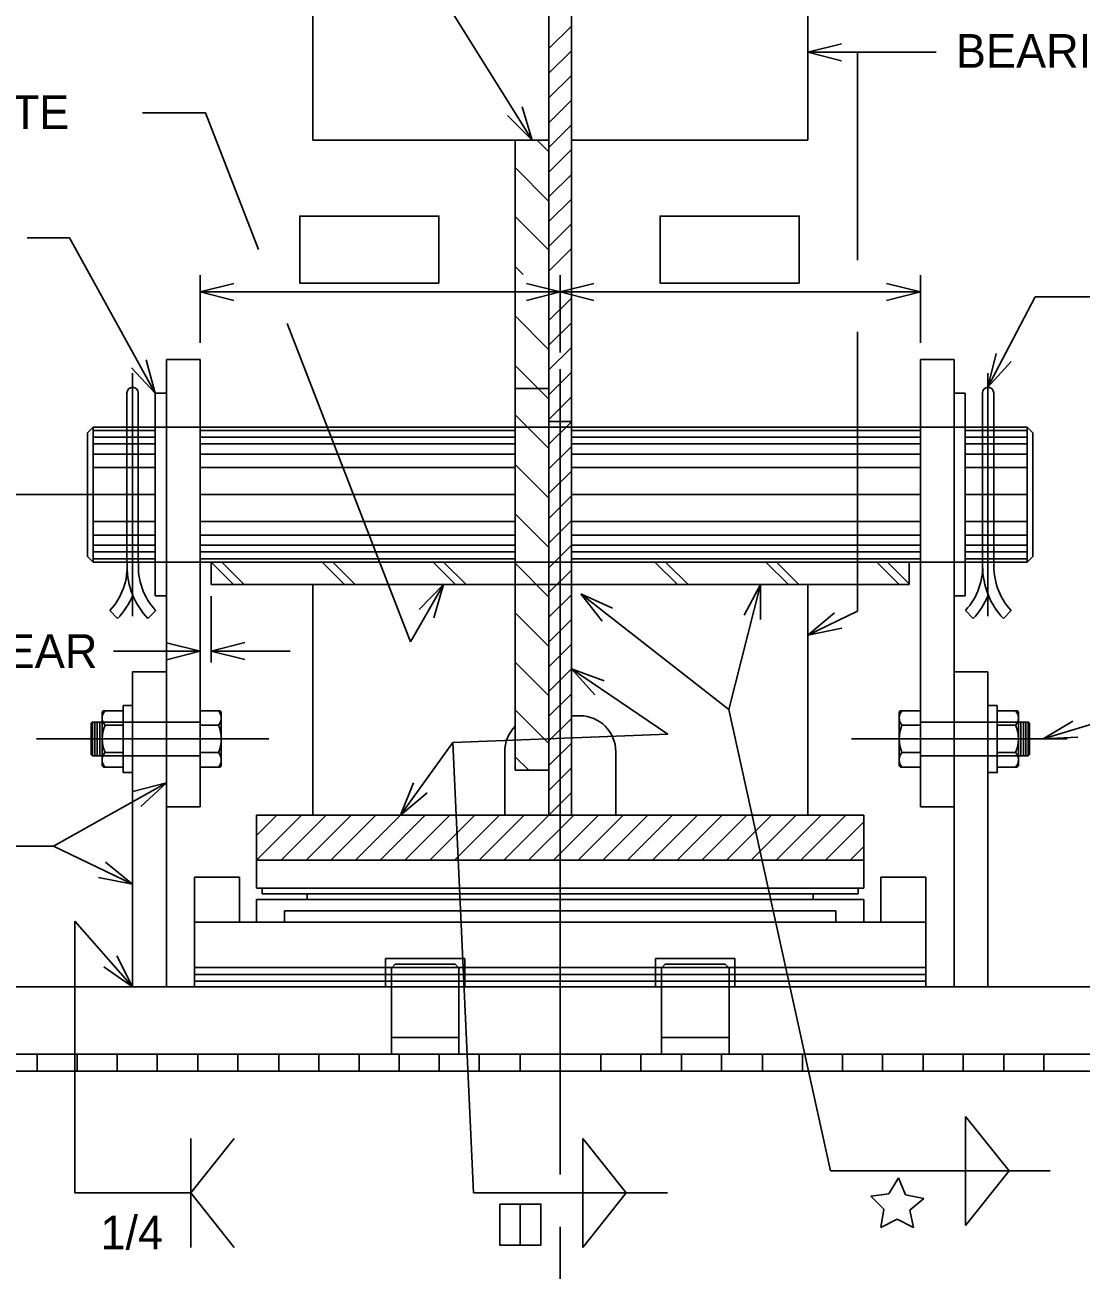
# Model space of a CAD drawing. Extents: x -1.5 to 34.7, y 2.5 to 26.9.
# Drawn here: x 12.425 to 16.336, y 17.426 to 22.038 of the extents above; entities that cross this region are included whole.
import ezdxf

# ---------------------------------------------------------------- set-up
doc = ezdxf.new("R2010")
doc.units = 0
doc.layers.add('Level 2', color=7, linetype='Continuous')

msp = doc.modelspace()

# ---------------------------------------------------------------- linework, layer by layer
at = {"layer": 'Level 2'}
for p, q in [((13.4904, 21.6108), (13.4904, 23.6955)), ((14.3654, 19.9649), (14.3654, 23.6955)), ((14.4487, 19.9649), (14.4487, 23.6955)), ((15.3237, 21.6108), (15.3237, 23.6955)), ((14.3029, 21.6108), (13.8837, 22.2818)), ((14.3654, 21.9503), (14.4487, 22.0336)), ((15.4487, 21.9676), (15.3237, 21.9364)), ((14.3654, 21.8587), (14.4487, 21.942)), ((15.7996, 21.9364), (15.3237, 21.9364)), ((15.4487, 21.9051), (15.3237, 21.9364)), ((15.5073, 21.166), (15.5073, 21.9364)), ((14.3654, 21.7671), (14.4487, 21.8504)), ((14.2661, 21.7342), (14.3029, 21.6108)), ((14.3654, 21.6755), (14.4487, 21.7589)), ((12.8605, 21.7119), (13.0936, 21.7119)), ((13.2893, 21.2064), (13.0936, 21.7119)), ((14.2123, 21.7024), (14.3029, 21.6108)), ((14.3654, 21.5839), (14.4487, 21.6673)), ((14.2404, 21.6108), (13.4904, 21.6108)), ((14.2404, 19.9649), (14.2404, 21.6108)), ((14.2404, 21.6108), (14.3654, 21.6108)), ((14.322, 21.6108), (14.3654, 21.5674)), ((14.4487, 21.6108), (15.3237, 21.6108)), ((14.3654, 21.4923), (14.4487, 21.5757)), ((14.2404, 21.5092), (14.3654, 21.3842)), ((14.3654, 21.4007), (14.4487, 21.4841)), ((14.3654, 21.3091), (14.4487, 21.3925)), ((14.2404, 21.3286), (14.3654, 21.2036)), ((14.3654, 21.2175), (14.4487, 21.3009)), ((12.4328, 21.2492), (12.5905, 21.2492)), ((12.5905, 21.2492), (12.907, 20.6732)), ((14.3654, 21.126), (14.4487, 21.2093)), ((14.2404, 21.1428), (14.2704, 21.1128)), ((13.0737, 21.1113), (13.0737, 20.8607)), ((13.1987, 21.0801), (13.0737, 21.0488)), ((14.282, 21.0801), (14.407, 21.0488)), ((14.407, 21.1113), (14.407, 20.8248)), ((14.532, 21.0801), (14.407, 21.0488)), ((15.6154, 21.0801), (15.7404, 21.0488)), ((15.7404, 21.1113), (15.7404, 20.8607)), ((13.0737, 21.0488), (14.407, 21.0488)), ((13.1987, 21.0176), (13.0737, 21.0488)), ((14.282, 21.0176), (14.407, 21.0488)), ((14.407, 21.0488), (15.7404, 21.0488)), ((14.532, 21.0176), (14.407, 21.0488)), ((15.6154, 21.0176), (15.7404, 21.0488)), ((16.1655, 21.0308), (15.9904, 20.6955)), ((16.3998, 21.0308), (16.1655, 21.0308)), ((14.3654, 20.9428), (14.4487, 21.0261)), ((14.2404, 20.9596), (14.3654, 20.8346)), ((13.8523, 19.7522), (13.3954, 20.9322)), ((14.3654, 20.8512), (14.4487, 20.9345)), ((15.5073, 19.8665), (15.5073, 20.9014)), ((14.3654, 20.7596), (14.4487, 20.8429)), ((15.9904, 20.6955), (16.0214, 20.8206)), ((12.8194, 20.7677), (12.907, 20.6732)), ((12.8742, 20.7978), (12.907, 20.6732)), ((12.9487, 19.1419), (12.9487, 20.7982)), ((13.0737, 20.7982), (12.9487, 20.7982)), ((13.0737, 19.1419), (13.0737, 20.7982)), ((14.2404, 20.7765), (14.3654, 20.6515)), ((14.407, 17.918), (14.407, 20.7623)), ((15.7404, 19.1419), (15.7404, 20.7982)), ((15.7404, 20.7982), (15.8654, 20.7982)), ((15.8654, 19.1419), (15.8654, 20.7982)), ((15.9904, 20.6955), (16.0766, 20.7913)), ((12.8237, 20.7482), (12.8237, 19.8482)), ((14.3654, 20.668), (14.4487, 20.7513)), ((15.9904, 20.7482), (15.9904, 19.8482)), ((12.8029, 20.6747), (12.8029, 20.5482)), ((12.8445, 20.6747), (12.8445, 20.5482)), ((12.907, 20.6732), (12.9487, 20.6732)), ((12.907, 20.6732), (12.907, 19.9232)), ((14.2404, 20.6916), (14.3654, 20.6916)), ((15.8654, 20.6732), (15.907, 20.6732)), ((15.907, 20.6732), (15.907, 19.9232)), ((15.9706, 20.6747), (15.9706, 20.5482)), ((16.0122, 20.6747), (16.0122, 20.5482)), ((12.9487, 20.6499), (12.9487, 19.9464)), ((14.3654, 20.5764), (14.4487, 20.6597)), ((15.8654, 20.6499), (15.8654, 19.9464)), ((14.2404, 20.5933), (14.3654, 20.4683)), ((12.6779, 20.5482), (12.657, 20.5274)), ((12.657, 20.5274), (12.657, 20.069)), ((12.6779, 20.5482), (12.6779, 20.0482)), ((12.907, 20.5482), (12.6779, 20.5482)), ((12.6779, 20.5357), (12.907, 20.5357)), ((12.8029, 20.5482), (12.8029, 20.0482)), ((12.8445, 20.5482), (12.8445, 20.0482)), ((13.0737, 20.5482), (12.907, 20.5482)), ((14.2404, 20.5482), (13.0737, 20.5482)), ((13.0737, 20.5357), (14.2404, 20.5357)), ((14.4487, 20.5482), (14.2404, 20.5482)), ((14.3654, 20.569), (14.4487, 20.569)), ((14.3654, 20.4848), (14.4487, 20.5681)), ((15.7404, 20.5482), (14.4487, 20.5482)), ((14.4487, 20.5357), (15.7404, 20.5357)), ((15.907, 20.5482), (15.7404, 20.5482)), ((16.1362, 20.5482), (15.907, 20.5482)), ((15.907, 20.5357), (16.1362, 20.5357)), ((15.9706, 20.5482), (15.9706, 20.0482)), ((16.0122, 20.5482), (16.0122, 20.0482)), ((16.1362, 20.5482), (16.157, 20.5274)), ((16.1362, 20.5482), (16.1362, 20.0482)), ((16.157, 20.069), (16.157, 20.5274)), ((12.6779, 20.5107), (12.907, 20.5107)), ((12.6779, 20.4857), (12.907, 20.4857)), ((13.0737, 20.5107), (14.2404, 20.5107)), ((13.0737, 20.4857), (14.2404, 20.4857)), ((14.4487, 20.5107), (15.7404, 20.5107)), ((14.4487, 20.4857), (15.7404, 20.4857)), ((15.907, 20.5107), (16.1362, 20.5107)), ((15.907, 20.4857), (16.1362, 20.4857)), ((12.6779, 20.4482), (12.907, 20.4482)), ((13.0737, 20.4482), (14.2404, 20.4482)), ((14.3654, 20.3932), (14.4487, 20.4765)), ((14.4487, 20.4482), (15.7404, 20.4482)), ((15.907, 20.4482), (16.1362, 20.4482)), ((12.6779, 20.3982), (12.907, 20.3982)), ((13.0737, 20.3982), (14.2404, 20.3982)), ((14.2404, 20.4101), (14.3654, 20.2851)), ((14.4487, 20.3982), (15.7404, 20.3982)), ((15.907, 20.3982), (16.1362, 20.3982)), ((14.3654, 20.3016), (14.4487, 20.3849)), ((12.0203, 20.2982), (12.7984, 20.2982)), ((12.6779, 20.2982), (12.907, 20.2982)), ((13.0737, 20.2982), (14.2404, 20.2982)), ((14.3654, 20.21), (14.4487, 20.2933)), ((14.4487, 20.2982), (15.7404, 20.2982)), ((15.907, 20.2982), (16.1362, 20.2982)), ((14.2404, 20.2269), (14.3654, 20.1019)), ((14.3654, 20.1184), (14.4487, 20.2017)), ((12.6779, 20.1982), (12.907, 20.1982)), ((13.0737, 20.1982), (14.2404, 20.1982)), ((14.4487, 20.1982), (15.7404, 20.1982)), ((15.907, 20.1982), (16.1362, 20.1982)), ((12.6779, 20.1482), (12.907, 20.1482)), ((12.6779, 20.1107), (12.907, 20.1107)), ((13.0737, 20.1482), (14.2404, 20.1482)), ((13.0737, 20.1107), (14.2404, 20.1107)), ((14.3654, 20.0268), (14.4487, 20.1102)), ((14.4487, 20.1482), (15.7404, 20.1482)), ((14.4487, 20.1107), (15.7404, 20.1107)), ((15.907, 20.1482), (16.1362, 20.1482)), ((15.907, 20.1107), (16.1362, 20.1107)), ((12.657, 20.069), (12.6779, 20.0482)), ((12.6779, 20.0857), (12.907, 20.0857)), ((13.0737, 20.0857), (14.2404, 20.0857)), ((14.4487, 20.0857), (15.7404, 20.0857)), ((15.907, 20.0857), (16.1362, 20.0857)), ((16.157, 20.069), (16.1362, 20.0482)), ((12.6779, 20.0607), (12.907, 20.0607)), ((12.6779, 20.0482), (12.907, 20.0482)), ((12.907, 20.0482), (13.0737, 20.0482)), ((13.0737, 20.0607), (14.2404, 20.0607)), ((13.0737, 20.0482), (14.2404, 20.0482)), ((13.1144, 20.0482), (13.1144, 19.9649)), ((13.1144, 20.0482), (13.1978, 19.9649)), ((13.1537, 20.0482), (13.237, 19.9649)), ((13.5252, 20.0482), (13.6086, 19.9649)), ((13.5645, 20.0482), (13.6478, 19.9649)), ((13.936, 20.0482), (14.0193, 19.9649)), ((13.9753, 20.0482), (14.0586, 19.9649)), ((14.2404, 20.0482), (14.4487, 20.0482)), ((14.2404, 20.0437), (14.3654, 19.9187)), ((14.3654, 19.9352), (14.4487, 20.0186)), ((14.4487, 20.0607), (15.7404, 20.0607)), ((14.4487, 20.0482), (15.7404, 20.0482)), ((14.7576, 20.0482), (14.8409, 19.9649)), ((14.7968, 20.0482), (14.8802, 19.9649)), ((15.1684, 20.0482), (15.2517, 19.9649)), ((15.2076, 20.0482), (15.291, 19.9649)), ((15.5792, 20.0482), (15.6625, 19.9649)), ((15.6184, 20.0482), (15.6996, 19.967)), ((15.6996, 20.0482), (15.6996, 19.9649)), ((15.7404, 20.0482), (15.907, 20.0482)), ((15.907, 20.0607), (16.1362, 20.0607)), ((15.907, 20.0482), (16.1362, 20.0482)), ((14.2404, 19.9649), (13.1144, 19.9649)), ((13.4904, 19.9649), (13.4904, 19.1107)), ((13.8523, 19.7522), (13.9751, 19.9649)), ((13.9751, 19.9649), (13.8852, 19.8725)), ((13.9751, 19.9649), (13.9392, 19.8411)), ((14.2404, 19.2774), (14.2404, 19.9649)), ((14.4487, 19.9649), (14.2404, 19.9649)), ((14.3654, 19.1107), (14.3654, 19.9649)), ((14.3654, 19.8436), (14.4487, 19.927)), ((14.4487, 19.1107), (14.4487, 19.9649)), ((15.6996, 19.9649), (14.4487, 19.9649)), ((15.0313, 19.5016), (14.4834, 19.9307)), ((14.4834, 19.9307), (14.5623, 19.8289)), ((14.4834, 19.9307), (14.601, 19.878)), ((15.0313, 19.5016), (15.1484, 19.9649)), ((15.0875, 19.8513), (15.1484, 19.9649)), ((15.1481, 19.836), (15.1484, 19.9649)), ((15.3237, 19.9649), (15.3237, 19.1107)), ((12.907, 19.9232), (12.9487, 19.9232)), ((13.1144, 19.9218), (13.1144, 19.6766)), ((15.8654, 19.9232), (15.907, 19.9232)), ((12.7395, 19.8688), (12.7682, 19.8386)), ((12.9091, 19.8688), (12.8803, 19.8386)), ((14.2404, 19.8605), (14.3654, 19.7355)), ((14.3654, 19.752), (14.4487, 19.8354)), ((15.3237, 19.7769), (15.5073, 19.8665)), ((15.3237, 19.7769), (15.4224, 19.8598)), ((15.9072, 19.8688), (15.9359, 19.8386)), ((16.0767, 19.8688), (16.048, 19.8386)), ((15.3237, 19.7769), (15.4498, 19.8036)), ((13.0737, 19.7179), (12.9487, 19.7491)), ((13.1144, 19.7186), (13.2394, 19.7499)), ((14.3654, 19.6604), (14.4487, 19.7438)), ((15.8654, 19.7703), (15.8654, 19.7391)), ((12.7533, 19.7179), (13.0737, 19.7179)), ((13.0737, 19.7179), (12.9487, 19.6866)), ((13.1144, 19.7186), (13.2394, 19.6874)), ((13.1144, 19.7186), (13.4076, 19.7186)), ((15.8654, 19.7391), (15.8654, 19.7078)), ((14.2404, 19.6773), (14.3654, 19.5523)), ((14.3654, 19.5688), (14.4487, 19.6522)), ((14.4487, 19.6522), (14.5349, 19.5564)), ((14.4487, 19.6522), (14.5698, 19.6082)), ((14.8049, 19.4102), (14.4487, 19.6522)), ((12.9487, 19.6419), (12.8237, 19.6419)), ((12.8237, 18.4753), (12.8237, 19.6419)), ((12.9487, 18.4753), (12.9487, 19.6419)), ((15.8654, 19.6419), (15.9904, 19.6419)), ((15.8654, 18.4753), (15.8654, 19.6419)), ((15.9904, 18.4753), (15.9904, 19.6419)), ((16.9035, 19.6085), (16.1949, 19.393)), ((14.3654, 19.4773), (14.4487, 19.5606)), ((12.711, 19.4931), (12.7155, 19.4976)), ((12.711, 19.2929), (12.711, 19.4931)), ((12.7155, 19.4976), (12.7893, 19.4976)), ((13.0737, 19.4976), (13.1476, 19.4976)), ((13.0737, 19.2884), (13.0737, 19.4976)), ((13.1521, 19.4931), (13.1476, 19.4976)), ((13.1521, 19.4931), (13.1521, 19.2929)), ((14.2404, 19.5006), (14.3654, 19.3756)), ((14.3654, 19.3857), (14.4487, 19.469)), ((14.4795, 19.4789), (14.4487, 19.4789)), ((15.0313, 19.5016), (15.4079, 17.793)), ((15.662, 19.4931), (15.6665, 19.4976)), ((15.662, 19.4931), (15.662, 19.2929)), ((15.7404, 19.4976), (15.6665, 19.4976)), ((15.7404, 19.2884), (15.7404, 19.4976)), ((16.0991, 19.4976), (16.0253, 19.4976)), ((16.1036, 19.4931), (16.0991, 19.4976)), ((16.1036, 19.2929), (16.1036, 19.4931)), ((12.6748, 19.4555), (12.6703, 19.451)), ((12.6703, 19.335), (12.6703, 19.451)), ((12.6748, 19.4555), (12.71, 19.4555)), ((12.6748, 19.4555), (12.6748, 19.3305)), ((12.6838, 19.4555), (12.6838, 19.3305)), ((12.6928, 19.4555), (12.6928, 19.3305)), ((12.7018, 19.4555), (12.7018, 19.3305)), ((12.711, 19.4555), (12.8237, 19.4555)), ((12.7214, 19.4436), (12.7893, 19.4436)), ((12.8237, 19.4555), (13.0737, 19.4555)), ((13.0737, 19.4436), (13.1416, 19.4436)), ((15.7404, 19.4436), (15.6725, 19.4436)), ((15.9904, 19.4555), (15.7404, 19.4555)), ((16.1036, 19.4555), (15.9909, 19.4555)), ((16.0932, 19.4436), (16.0253, 19.4436)), ((16.1398, 19.4555), (16.1046, 19.4555)), ((16.1128, 19.4555), (16.1128, 19.3305)), ((16.1218, 19.4555), (16.1218, 19.3305)), ((16.1308, 19.4555), (16.1308, 19.3305)), ((16.1398, 19.4555), (16.1443, 19.451)), ((16.1398, 19.4555), (16.1398, 19.3305)), ((16.1443, 19.335), (16.1443, 19.451)), ((16.3054, 19.4593), (16.1949, 19.393)), ((13.3282, 19.393), (12.4677, 19.393)), ((14.0092, 19.3795), (13.8156, 19.1107)), ((14.0092, 19.3795), (14.8049, 19.4102)), ((14.0092, 19.3795), (14.0861, 17.7115)), ((14.3654, 19.2941), (14.4487, 19.3774)), ((15.4859, 19.393), (16.2838, 19.393)), ((16.3236, 19.3995), (16.1949, 19.393)), ((12.6703, 19.335), (12.6748, 19.3305)), ((12.71, 19.3305), (12.6748, 19.3305)), ((12.711, 19.3305), (12.8237, 19.3305)), ((12.7893, 19.3424), (12.7214, 19.3424)), ((12.8237, 19.3305), (13.0737, 19.3305)), ((13.1416, 19.3424), (13.0737, 19.3424)), ((14.2015, 19.3458), (14.2015, 19.1107)), ((14.2404, 19.3273), (14.2902, 19.2774)), ((14.6126, 19.3458), (14.6126, 19.1107)), ((15.6725, 19.3424), (15.7404, 19.3424)), ((15.9904, 19.3305), (15.7404, 19.3305)), ((16.1036, 19.3305), (15.9909, 19.3305)), ((16.0253, 19.3424), (16.0932, 19.3424)), ((16.1046, 19.3305), (16.1398, 19.3305)), ((16.1443, 19.335), (16.1398, 19.3305)), ((12.711, 19.2929), (12.7155, 19.2884)), ((12.7893, 19.2884), (12.7155, 19.2884)), ((13.1476, 19.2884), (13.0737, 19.2884)), ((13.1521, 19.2929), (13.1476, 19.2884)), ((14.3654, 19.2025), (14.4487, 19.2858)), ((15.662, 19.2929), (15.6665, 19.2884)), ((15.6665, 19.2884), (15.7404, 19.2884)), ((16.0253, 19.2884), (16.0991, 19.2884)), ((16.1036, 19.2929), (16.0991, 19.2884)), ((14.2404, 19.2774), (14.3654, 19.2774)), ((12.5309, 18.9964), (12.9487, 19.2311)), ((12.9487, 19.2311), (12.8242, 19.1978)), ((12.9487, 19.2311), (12.8545, 19.1431)), ((13.8633, 19.2304), (13.8156, 19.1107)), ((13.914, 19.1939), (13.8156, 19.1107)), ((14.3652, 19.1107), (14.4487, 19.1942)), ((13.0737, 19.1419), (12.9487, 19.1419)), ((15.7404, 19.1419), (15.8654, 19.1419)), ((13.2826, 19.1107), (15.5315, 19.1107)), ((13.2826, 18.944), (13.2826, 19.1107)), ((13.2826, 19.0356), (13.3577, 19.1107)), ((13.2826, 18.944), (13.4493, 19.1107)), ((13.3742, 18.944), (13.5408, 19.1107)), ((13.4658, 18.944), (13.6324, 19.1107)), ((13.5574, 18.944), (13.724, 19.1107)), ((13.649, 18.944), (13.8156, 19.1107)), ((13.7406, 18.944), (13.9072, 19.1107)), ((13.8322, 18.944), (13.9988, 19.1107)), ((13.9237, 18.944), (14.0904, 19.1107)), ((14.0153, 18.944), (14.182, 19.1107)), ((14.1069, 18.944), (14.2736, 19.1107)), ((14.1985, 18.944), (14.3652, 19.1107)), ((14.2901, 18.944), (14.4568, 19.1107)), ((14.3817, 18.944), (14.5484, 19.1107)), ((14.4733, 18.944), (14.64, 19.1107)), ((14.5649, 18.944), (14.7316, 19.1107)), ((14.6565, 18.944), (14.8232, 19.1107)), ((14.7481, 18.944), (14.9148, 19.1107)), ((14.8397, 18.944), (15.0064, 19.1107)), ((14.9313, 18.944), (15.098, 19.1107)), ((15.0229, 18.944), (15.1895, 19.1107)), ((15.1145, 18.944), (15.2811, 19.1107)), ((15.2061, 18.944), (15.3727, 19.1107)), ((15.2977, 18.944), (15.4643, 19.1107)), ((15.5315, 19.1107), (15.5315, 18.944)), ((15.3893, 18.944), (15.5315, 19.0863)), ((12.5309, 18.9964), (12.0887, 18.9964)), ((12.5309, 18.9964), (12.8237, 18.8551)), ((15.4809, 18.944), (15.5315, 18.9947)), ((12.8237, 18.8551), (12.7236, 18.9362)), ((15.5315, 18.944), (13.2826, 18.944)), ((13.2826, 18.944), (13.2826, 18.8399)), ((15.5315, 18.944), (15.5315, 18.8399)), ((12.8237, 18.8551), (12.6972, 18.8796)), ((13.0529, 18.8815), (13.0529, 18.4753)), ((13.2195, 18.8815), (13.0529, 18.8815)), ((13.2195, 18.8815), (13.2195, 18.7149)), ((15.5945, 18.8815), (15.5945, 18.7149)), ((15.5945, 18.8815), (15.7612, 18.8815)), ((15.7612, 18.8815), (15.7612, 18.4753)), ((15.5315, 18.8399), (13.2826, 18.8399)), ((13.3034, 18.8399), (13.3034, 18.819)), ((15.5107, 18.819), (13.3034, 18.819)), ((15.407, 18.819), (13.407, 18.819)), ((13.47, 18.819), (13.47, 18.7982)), ((15.3441, 18.819), (15.3441, 18.7982)), ((15.5107, 18.8399), (15.5107, 18.819)), ((15.5315, 18.7982), (13.2826, 18.7982)), ((13.2826, 18.7982), (13.2826, 18.7149)), ((15.5315, 18.7982), (15.5315, 18.7149)), ((13.3862, 18.7565), (13.3862, 18.7149)), ((15.4279, 18.7565), (13.3862, 18.7565)), ((15.4279, 18.7565), (15.4279, 18.7149)), ((12.6102, 17.7115), (12.6102, 18.7183)), ((12.6102, 18.7183), (12.8237, 18.4753)), ((15.7612, 18.7149), (13.0529, 18.7149)), ((13.3862, 18.7149), (13.2404, 18.7149)), ((13.3862, 18.7149), (15.4279, 18.7149)), ((15.5737, 18.7149), (15.4279, 18.7149)), ((12.7647, 18.5898), (12.8237, 18.4753)), ((12.7177, 18.5486), (12.8237, 18.4753)), ((13.0529, 18.5462), (15.7612, 18.5462)), ((13.7601, 18.4753), (13.7601, 18.5794)), ((14.0539, 18.5794), (13.7601, 18.5794)), ((13.782, 18.5446), (13.796, 18.5586)), ((13.782, 18.5446), (13.782, 18.2253)), ((13.796, 18.5586), (14.018, 18.5586)), ((14.032, 18.5446), (14.018, 18.5586)), ((14.032, 18.5446), (14.032, 18.2253)), ((14.0539, 18.4753), (14.0539, 18.5794)), ((14.7601, 18.4753), (14.7601, 18.5794)), ((15.0539, 18.5794), (14.7601, 18.5794)), ((14.782, 18.5446), (14.796, 18.5586)), ((14.782, 18.5446), (14.782, 18.2253)), ((14.796, 18.5586), (15.018, 18.5586)), ((15.032, 18.5446), (15.018, 18.5586)), ((15.032, 18.5446), (15.032, 18.2253)), ((15.0539, 18.4753), (15.0539, 18.5794)), ((13.0529, 18.52), (15.7612, 18.52)), ((13.0529, 18.4955), (15.7612, 18.4955)), ((17.0217, 18.4753), (11.7924, 18.4753)), ((15.7612, 18.4753), (13.0529, 18.4753)), ((13.782, 18.2878), (14.032, 18.2878)), ((14.782, 18.2878), (15.032, 18.2878)), ((17.0217, 18.2253), (11.7924, 18.2253)), ((9.9734, 18.1626), (18.3775, 18.1626)), ((16.0687, 17.793), (15.9081, 17.9949)), ((15.9081, 17.9949), (15.9081, 17.5912)), ((13.0395, 17.7115), (13.2, 17.9133)), ((13.0395, 17.9133), (13.0395, 17.5096)), ((14.407, 17.7798), (14.407, 17.918)), ((14.4909, 17.9133), (14.4909, 17.5096)), ((14.6514, 17.7115), (14.4909, 17.9133)), ((15.4079, 17.793), (16.2207, 17.793)), ((15.6242, 17.7084), (15.6597, 17.768)), ((15.6597, 17.768), (15.686, 17.7049)), ((16.0687, 17.793), (15.9081, 17.5912)), ((13.0395, 17.7115), (12.6102, 17.7115)), ((13.0395, 17.7115), (13.2, 17.5096)), ((14.0861, 17.7115), (14.8045, 17.7115)), ((14.4909, 17.5096), (14.6514, 17.7115)), ((15.5569, 17.6999), (15.6242, 17.7084)), ((15.6048, 17.6512), (15.5569, 17.6999)), ((15.686, 17.7049), (15.7534, 17.6912)), ((15.7534, 17.6912), (15.7017, 17.6479)), ((15.5946, 17.5836), (15.6048, 17.6512)), ((15.7017, 17.6479), (15.7148, 17.5836)), ((14.407, 16.9142), (14.407, 17.5856)), ((15.6547, 17.6145), (15.5946, 17.5836)), ((15.7148, 17.5836), (15.6547, 17.6145))]:
    msp.add_line(p, q, dxfattribs=at)
for points in [[(13.9576, 21.0816), (13.9576, 21.3296), (13.4423, 21.3296), (13.4423, 21.0816)], [(15.2922, 21.0816), (15.2922, 21.3296), (14.7769, 21.3296), (14.7769, 21.0816)], [(12.7893, 19.5173), (12.7893, 19.2687), (12.8237, 19.2687), (12.8237, 19.5173)], [(16.0253, 19.5173), (16.0253, 19.2687), (15.9909, 19.2687), (15.9909, 19.5173)], [(12.4708, 18.2253), (12.6189, 18.2253), (12.6189, 18.1626), (12.4708, 18.1626)], [(12.7666, 18.2253), (12.9147, 18.2253), (12.9147, 18.1626), (12.7666, 18.1626)], [(13.0646, 18.2253), (13.2127, 18.2253), (13.2127, 18.1626), (13.0646, 18.1626)], [(13.3648, 18.2253), (13.5129, 18.2253), (13.5129, 18.1626), (13.3648, 18.1626)], [(13.6628, 18.2253), (13.8109, 18.2253), (13.8109, 18.1626), (13.6628, 18.1626)], [(13.9585, 18.2253), (14.1066, 18.2253), (14.1066, 18.1626), (13.9585, 18.1626)], [(14.259, 18.2253), (14.4071, 18.2253), (14.4071, 18.1626), (14.259, 18.1626)], [(14.5575, 18.2253), (14.7056, 18.2253), (14.7056, 18.1626), (14.5575, 18.1626)], [(14.8555, 18.2253), (15.0036, 18.2253), (15.0036, 18.1626), (14.8555, 18.1626)], [(15.1557, 18.2253), (15.3038, 18.2253), (15.3038, 18.1626), (15.1557, 18.1626)], [(15.4522, 18.2253), (15.6003, 18.2253), (15.6003, 18.1626), (15.4522, 18.1626)], [(15.751, 18.2253), (15.899, 18.2253), (15.899, 18.1626), (15.751, 18.1626)], [(16.0497, 18.2253), (16.1978, 18.2253), (16.1978, 18.1626), (16.0497, 18.1626)], [(14.183, 17.6704), (14.3357, 17.6704), (14.3357, 17.5184), (14.183, 17.5184)], [(14.2593, 17.6704), (14.3357, 17.6704), (14.3357, 17.5184), (14.2593, 17.5184)]]:
    msp.add_lwpolyline(points, close=True, dxfattribs=at)
for centre, radius, start, end in [((12.8237, 20.6747), 0.0208, 0, 180), ((15.9914, 20.6747), 0.0208, 0, 180), ((12.5647, 20.0315), 0.2388, 317.0584, 4.0171), ((13.0838, 20.0315), 0.2804, 180, 223.4565), ((13.0838, 20.0315), 0.2388, 175.9829, 222.9416), ((15.7324, 20.0315), 0.2388, 317.0584, 4.0171), ((16.2515, 20.0315), 0.2804, 180, 223.4565), ((16.2515, 20.0315), 0.2388, 175.9829, 222.9416), ((12.5647, 20.0315), 0.2804, 316.5435, 337.7905), ((15.7324, 20.0315), 0.2804, 316.5435, 337.7905), ((12.751, 19.4706), 0.0401, 137.6444, 222.3556), ((13.112, 19.4706), 0.0401, 317.6444, 42.3556), ((14.4795, 19.3458), 0.1331, 0, 90), ((15.7021, 19.4706), 0.0401, 137.6444, 222.3556), ((16.0636, 19.4706), 0.0401, 317.6444, 42.3556), ((12.8387, 19.393), 0.1277, 156.6507, 203.3493), ((13.0243, 19.393), 0.1277, 336.6507, 23.3493), ((14.3346, 19.3458), 0.1331, 135.061, 180), ((15.7897, 19.393), 0.1277, 156.6507, 203.3493), ((15.9759, 19.393), 0.1277, 336.6507, 23.3493), ((12.751, 19.3154), 0.0401, 137.6444, 222.3556), ((13.112, 19.3154), 0.0401, 317.6444, 42.3556), ((15.7021, 19.3154), 0.0401, 137.6444, 222.3556), ((16.0636, 19.3154), 0.0401, 317.6444, 42.3556)]:
    msp.add_arc(centre, radius, start, end, dxfattribs=at)

# ---------------------------------------------------------------- texts
for s, p in [('BEARING STIFFENER', (15.8717, 21.8788)), ('PIN BEARING pLATE', (10.9545, 21.6522)), ('1/8" CLEAR', (11.798, 19.6561)), ('1/4', (12.7044, 17.5022))]:
    msp.add_text(s, height=0.125, dxfattribs=at).set_placement(p)

doc.saveas('drawing.dxf')
